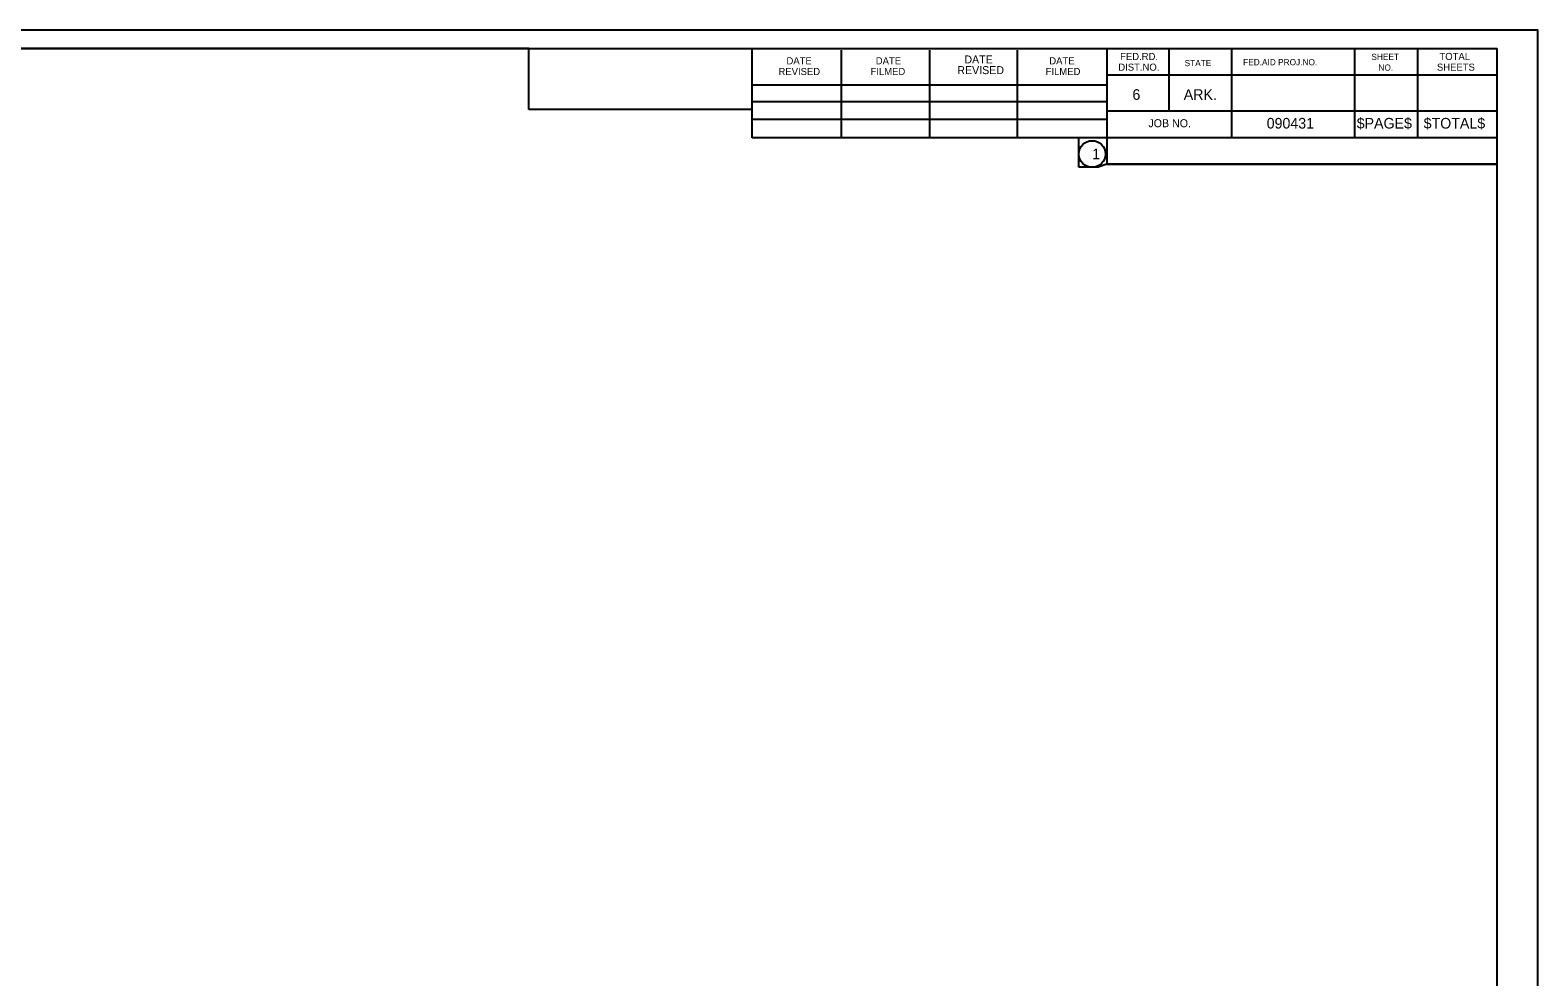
# Model space of a CAD drawing. Extents: x -1.3 to 32.1, y -0.2 to 20.7.
# Drawn here: x 15.42 to 32.07, y 10.29 to 20.75 of the extents above; entities that cross this region are included whole.
import ezdxf

# ---------------------------------------------------------------- set-up
doc = ezdxf.new("R2010")
doc.units = 0
for name, color, linetype in [('Level 1', 7, 'Continuous'), ('Level 1a', 7, 'Continuous'), ('Level 24', 7, 'Continuous'), ('Level 62', 7, 'Continuous'), ('Level 63', 7, 'Continuous')]:
    doc.layers.add(name, color=color, linetype=linetype)

msp = doc.modelspace()

# ---------------------------------------------------------------- linework, layer by layer
at = {"layer": 'Level 1'}
for p, q in [((-0.001, 20.545), (31.617, 20.545)), ((23.391, 19.557), (23.391, 20.545)), ((24.377, 19.557), (24.377, 20.525)), ((25.353, 19.557), (25.353, 20.525)), ((26.321, 19.557), (26.321, 20.525)), ((27.307, 20.545), (27.307, 19.265)), ((27.991, 20.545), (27.991, 19.851)), ((28.685, 20.545), (28.685, 19.557)), ((30.043, 20.545), (30.043, 19.557)), ((30.737, 20.545), (30.737, 19.557)), ((31.617, -0.001), (31.617, 20.545)), ((23.391, 20.143), (27.307, 20.143)), ((31.617, 20.251), (27.307, 20.251)), ((31.617, 20.253), (31.617, 20.253)), ((23.391, 19.957), (27.307, 19.957)), ((31.617, 19.851), (27.307, 19.851)), ((23.391, 19.557), (23.391, 19.763)), ((23.391, 19.763), (27.307, 19.763)), ((31.617, 19.557), (23.391, 19.557))]:
    msp.add_line(p, q, dxfattribs=at)
msp.add_circle((27.146, 19.379), 0.147, dxfattribs=at)
at = {"layer": 'Level 1a'}
msp.add_line((27.307, 19.265), (31.617, 19.265), dxfattribs=at)
at = {"layer": 'Level 24'}
for p, q in [((27, 19.558), (23.392, 19.558)), ((27, 19.233), (27, 19.558)), ((27.212, 19.233), (27, 19.233)), ((27.308, 19.266), (27.212, 19.233)), ((31.618, 19.266), (27.308, 19.266)), ((31.618, 10.293), (31.618, 19.266))]:
    msp.add_line(p, q, dxfattribs=at)
for points in [[(20.927, 19.872), (20.927, 20.545), (-0.001, 20.545)], [(23.392, 19.558), (23.391, 19.872), (20.927, 19.872)]]:
    msp.add_lwpolyline(points, dxfattribs=at)
at = {"layer": 'Level 62'}
for p, q in [((27, 19.558), (23.392, 19.558)), ((27, 19.233), (27, 19.558)), ((27.212, 19.233), (27, 19.233)), ((27.308, 19.266), (27.212, 19.233)), ((31.618, 19.266), (27.308, 19.266)), ((31.618, 10.294), (31.618, 19.266)), ((31.618, 0), (31.618, 10.294))]:
    msp.add_line(p, q, dxfattribs=at)
for points in [[(20.927, 19.872), (20.927, 20.545), (0, 20.546)], [(23.392, 19.558), (23.391, 19.872), (20.927, 19.872)]]:
    msp.add_lwpolyline(points, dxfattribs=at)
at = {"layer": 'Level 63'}
msp.add_lwpolyline([(-1.263, -0.2), (32.067, -0.2), (32.067, 20.746), (-1.263, 20.746)], close=True, dxfattribs=at)

# ---------------------------------------------------------------- texts
at = {"layer": 'Level 1'}
for s, height, p in [('FED.RD.', 0.0782, (27.455, 20.417)), ('SHEET', 0.0684, (30.229, 20.417)), ('TOTAL', 0.0782, (30.981, 20.417)), ('REVISED', 0.0782, (23.683, 20.251)), ('DATE', 0.0782, (23.771, 20.369)), ('FILMED', 0.0782, (24.699, 20.251)), ('DATE', 0.0782, (24.757, 20.369)), ('REVISED', 0.0879, (25.657, 20.261)), ('DATE', 0.0879, (25.735, 20.379)), ('FILMED', 0.0782, (26.633, 20.251)), ('DATE', 0.0782, (26.673, 20.369)), ('DIST.NO.', 0.0782, (27.435, 20.299)), ('STATE', 0.0684, (28.167, 20.349)), ('FED.AID PROJ.NO.', 0.0684, (28.813, 20.359)), ('NO.', 0.0684, (30.307, 20.299)), ('SHEETS', 0.0782, (30.953, 20.299)), ('6', 0.117, (27.591, 19.977)), ('ARK.', 0.1172, (28.157, 19.977)), ('JOB NO.', 0.0879, (27.767, 19.675)), ('090431', 0.1172, (29.073, 19.66)), ('$PAGE$', 0.1172, (30.067, 19.66)), ('$TOTAL$', 0.1172, (30.806, 19.66)), ('1', 0.117, (27.146, 19.321))]:
    msp.add_text(s, height=height, dxfattribs=at).set_placement(p)

doc.saveas('drawing.dxf')
